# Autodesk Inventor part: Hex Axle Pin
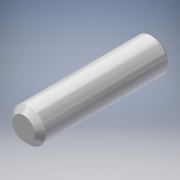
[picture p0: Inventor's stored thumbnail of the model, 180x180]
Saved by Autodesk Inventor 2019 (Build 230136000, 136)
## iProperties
Shininess: 50.0
Compacted: True
Length Units: 11272
Angle Units: 11279
Time Units: 11290
Mass Units: 11286
Length Display Precision: 4
Angle Display Precision: 2
Company: Autodesk
Created: 2000-05
Part Number: Hex Axle Pin
Project: Inventor Samples
User Status: IN PROGRESS
Document SubType Name: Modeling
Designer: Autodesk, Inc.
Density: 8.08 g/cm^3
Material: Stainless Steel
Mass: 0.334911 g
Surface Area: 0.764457 cm^2
Volume: 0.0414493 cm^3
Appearance: Steel
Density: 0.0
Volumn: 0.0
Area: 0.0
PropertySet Name: Model Information
Control State: 0
Master: False
Checked Out: False
Checked Out Date: 2018-05-30
Last Check In Date: 2018-05-30
Author: Autodesk, Inc.
Revision Number: A
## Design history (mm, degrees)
node "Extrusion1" dims "d1" = 9.525, "d2" = 0
  sketch "Sketch2"
    geometry: C1 r 1.191 at (-3.356, -2.398)
    constraints: 1 centre point
    dimensions: "d0" = 2.38125 diameter of C1
node "Chamfer1" dims "d3" = 0.381, "d4" = 0.381, "d6" = 45 deg
workplane "Work Plane1"
workaxis "Work Axis1"
workpoint "Work Point1"
body "Solid1"
other parameters: "d5" = -4.7625 (= -0.5 x d1)
